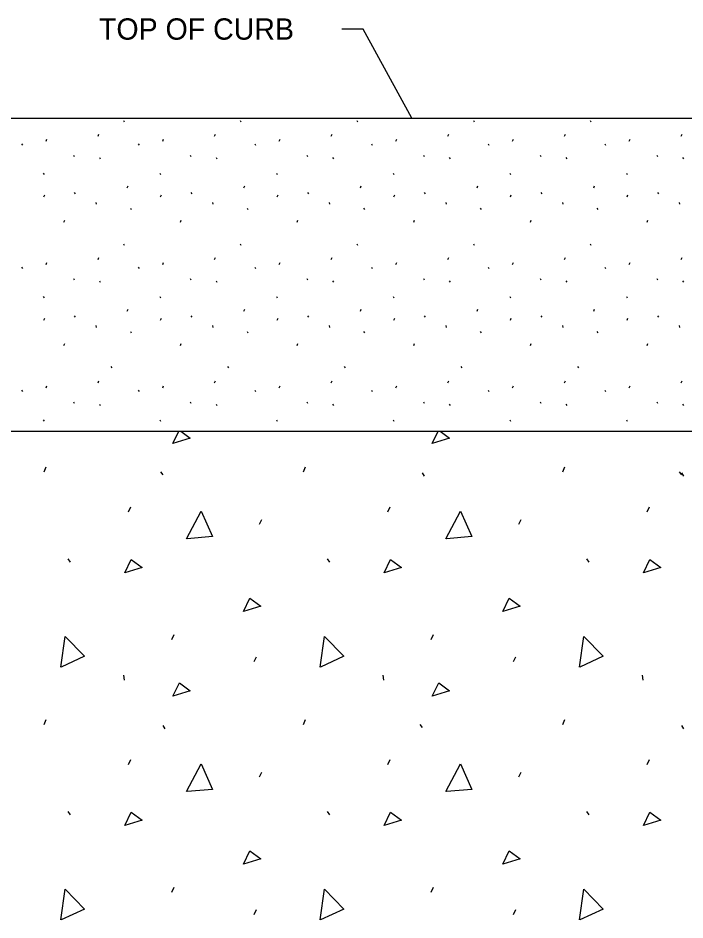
# Model space of a CAD drawing. Extents: x 99988 to 100172, y 99995 to 100047.
# Drawn here: x 100004.171 to 100006.359, y 100005.482 to 100008.443 of the extents above; entities that cross this region are included whole.
import ezdxf

# ---------------------------------------------------------------- set-up
doc = ezdxf.new("R2010")
doc.units = 0
for name, color, linetype in [('Level 1', 7, 'Continuous'), ('Level 15', 7, 'Continuous'), ('Level 2', 7, 'Continuous'), ('Level 20', 7, 'Continuous'), ('Level 3', 7, 'Continuous')]:
    doc.layers.add(name, color=color, linetype=linetype)

msp = doc.modelspace()

# ---------------------------------------------------------------- linework, layer by layer
at = {"layer": 'Level 1'}
msp.add_line((100000.585, 100008.1139), (100009.7707, 100008.1139), dxfattribs=at)
at = {"layer": 'Level 15'}
msp.add_lwpolyline([(100005.4633, 100008.1139), (100005.3031, 100008.407), (100005.2331, 100008.407)], dxfattribs=at)
at = {"layer": 'Level 2'}
msp.add_line((100000.585, 100007.0869), (100009.7707, 100007.0869), dxfattribs=at)
at = {"layer": 'Level 3'}
for p, q in [((100004.5171, 100008.1069), (100004.52, 100008.1026)), ((100004.8998, 100008.1069), (100004.9026, 100008.1026)), ((100005.2824, 100008.1069), (100005.2853, 100008.1026)), ((100005.665, 100008.1069), (100005.6679, 100008.1026)), ((100006.0477, 100008.1069), (100006.0506, 100008.1026)), ((100004.4337, 100008.0553), (100004.4366, 100008.0617)), ((100004.8164, 100008.0553), (100004.8192, 100008.0617)), ((100005.199, 100008.0553), (100005.2019, 100008.0617)), ((100005.5816, 100008.0553), (100005.5845, 100008.0617)), ((100005.9643, 100008.0553), (100005.9672, 100008.0617)), ((100006.3469, 100008.0553), (100006.3498, 100008.0617)), ((100004.1827, 100008.0303), (100004.1856, 100008.026)), ((100004.2632, 100008.0387), (100004.2661, 100008.0452)), ((100004.5654, 100008.0303), (100004.5683, 100008.026)), ((100004.6459, 100008.0387), (100004.6488, 100008.0452)), ((100004.948, 100008.0303), (100004.9509, 100008.026)), ((100005.0285, 100008.0387), (100005.0314, 100008.0452)), ((100005.3307, 100008.0303), (100005.3335, 100008.026)), ((100005.4112, 100008.0387), (100005.414, 100008.0452)), ((100005.7133, 100008.0303), (100005.7162, 100008.026)), ((100005.7938, 100008.0387), (100005.7967, 100008.0452)), ((100006.0959, 100008.0303), (100006.0988, 100008.026)), ((100006.1764, 100008.0387), (100006.1793, 100008.0452)), ((100004.3532, 100007.9927), (100004.356, 100007.9884)), ((100004.4382, 100007.9849), (100004.441, 100007.9806)), ((100004.7358, 100007.9927), (100004.7387, 100007.9884)), ((100004.8208, 100007.9849), (100004.8237, 100007.9806)), ((100005.1184, 100007.9927), (100005.1213, 100007.9884)), ((100005.2034, 100007.9849), (100005.2063, 100007.9806)), ((100005.5011, 100007.9927), (100005.504, 100007.9884)), ((100005.5861, 100007.9849), (100005.589, 100007.9806)), ((100005.8837, 100007.9927), (100005.8866, 100007.9884)), ((100005.9687, 100007.9849), (100005.9716, 100007.9806)), ((100006.2664, 100007.9927), (100006.2692, 100007.9884)), ((100006.3514, 100007.9849), (100006.3542, 100007.9806)), ((100004.2537, 100007.9338), (100004.2566, 100007.9295)), ((100004.6363, 100007.9338), (100004.6392, 100007.9295)), ((100005.019, 100007.9338), (100005.0218, 100007.9295)), ((100005.4016, 100007.9338), (100005.4045, 100007.9295)), ((100005.7842, 100007.9338), (100005.7871, 100007.9295)), ((100006.1669, 100007.9338), (100006.1698, 100007.9295)), ((100004.5294, 100007.8855), (100004.5322, 100007.892)), ((100004.912, 100007.8855), (100004.9149, 100007.892)), ((100005.2946, 100007.8855), (100005.2975, 100007.892)), ((100005.6773, 100007.8855), (100005.6802, 100007.892)), ((100006.0599, 100007.8855), (100006.0628, 100007.892)), ((100004.2561, 100007.856), (100004.2589, 100007.8625)), ((100004.3559, 100007.87), (100004.3587, 100007.8656)), ((100004.6387, 100007.856), (100004.6416, 100007.8625)), ((100004.7385, 100007.87), (100004.7414, 100007.8656)), ((100005.0213, 100007.856), (100005.0242, 100007.8625)), ((100005.1211, 100007.87), (100005.124, 100007.8656)), ((100005.404, 100007.856), (100005.4069, 100007.8625)), ((100005.5038, 100007.87), (100005.5067, 100007.8656)), ((100005.7866, 100007.856), (100005.7895, 100007.8625)), ((100005.8864, 100007.87), (100005.8893, 100007.8656)), ((100006.1693, 100007.856), (100006.1721, 100007.8625)), ((100006.2691, 100007.87), (100006.2719, 100007.8656)), ((100004.4271, 100007.8379), (100004.4278, 100007.8315)), ((100004.5398, 100007.8189), (100004.5427, 100007.8146)), ((100004.8097, 100007.8379), (100004.8104, 100007.8315)), ((100004.9225, 100007.8189), (100004.9253, 100007.8146)), ((100005.1923, 100007.8379), (100005.1931, 100007.8315)), ((100005.3051, 100007.8189), (100005.308, 100007.8146)), ((100005.575, 100007.8379), (100005.5757, 100007.8315)), ((100005.6878, 100007.8189), (100005.6906, 100007.8146)), ((100005.9576, 100007.8379), (100005.9583, 100007.8315)), ((100006.0704, 100007.8189), (100006.0733, 100007.8146)), ((100006.3403, 100007.8379), (100006.341, 100007.8315)), ((100004.3215, 100007.7726), (100004.3244, 100007.779)), ((100004.7042, 100007.7726), (100004.707, 100007.779)), ((100005.0868, 100007.7726), (100005.0897, 100007.779)), ((100005.4694, 100007.7726), (100005.4723, 100007.779)), ((100005.8521, 100007.7726), (100005.855, 100007.779)), ((100006.2347, 100007.7726), (100006.2376, 100007.779)), ((100004.5171, 100007.7022), (100004.52, 100007.6979)), ((100004.8998, 100007.7022), (100004.9026, 100007.6979)), ((100005.2824, 100007.7022), (100005.2853, 100007.6979)), ((100005.665, 100007.7022), (100005.6679, 100007.6979)), ((100006.0477, 100007.7022), (100006.0506, 100007.6979)), ((100004.2632, 100007.634), (100004.2661, 100007.6405)), ((100004.4337, 100007.6505), (100004.4366, 100007.657)), ((100004.6459, 100007.634), (100004.6488, 100007.6405)), ((100004.8164, 100007.6505), (100004.8192, 100007.657)), ((100005.0285, 100007.634), (100005.0314, 100007.6405)), ((100005.199, 100007.6505), (100005.2019, 100007.657)), ((100005.4112, 100007.634), (100005.414, 100007.6405)), ((100005.5816, 100007.6505), (100005.5845, 100007.657)), ((100005.7938, 100007.634), (100005.7967, 100007.6405)), ((100005.9643, 100007.6505), (100005.9672, 100007.657)), ((100006.1764, 100007.634), (100006.1793, 100007.6405)), ((100006.3469, 100007.6505), (100006.3498, 100007.657)), ((100004.1827, 100007.6256), (100004.1856, 100007.6213)), ((100004.5654, 100007.6256), (100004.5683, 100007.6213)), ((100004.948, 100007.6256), (100004.9509, 100007.6213)), ((100005.3307, 100007.6256), (100005.3335, 100007.6213)), ((100005.7133, 100007.6256), (100005.7162, 100007.6213)), ((100006.0959, 100007.6256), (100006.0988, 100007.6213)), ((100004.3532, 100007.588), (100004.356, 100007.5836)), ((100004.7358, 100007.588), (100004.7387, 100007.5836)), ((100005.1184, 100007.588), (100005.1213, 100007.5836)), ((100005.5011, 100007.588), (100005.504, 100007.5836)), ((100005.8837, 100007.588), (100005.8866, 100007.5836)), ((100006.2664, 100007.588), (100006.2692, 100007.5836)), ((100004.4382, 100007.5802), (100004.441, 100007.5759)), ((100004.8208, 100007.5802), (100004.8237, 100007.5759)), ((100005.2034, 100007.5802), (100005.2063, 100007.5759)), ((100005.5861, 100007.5802), (100005.589, 100007.5759)), ((100005.9687, 100007.5802), (100005.9716, 100007.5759)), ((100006.3514, 100007.5802), (100006.3542, 100007.5759)), ((100004.2537, 100007.5291), (100004.2566, 100007.5248)), ((100004.6363, 100007.5291), (100004.6392, 100007.5248)), ((100005.019, 100007.5291), (100005.0218, 100007.5248)), ((100005.4016, 100007.5291), (100005.4045, 100007.5248)), ((100005.7842, 100007.5291), (100005.7871, 100007.5248)), ((100006.1669, 100007.5291), (100006.1698, 100007.5248)), ((100004.3559, 100007.4652), (100004.3587, 100007.4609)), ((100004.5294, 100007.4808), (100004.5322, 100007.4873)), ((100004.7385, 100007.4652), (100004.7414, 100007.4609)), ((100004.912, 100007.4808), (100004.9149, 100007.4873)), ((100005.1211, 100007.4652), (100005.124, 100007.4609)), ((100005.2946, 100007.4808), (100005.2975, 100007.4873)), ((100005.5038, 100007.4652), (100005.5067, 100007.4609)), ((100005.6773, 100007.4808), (100005.6802, 100007.4873)), ((100005.8864, 100007.4652), (100005.8893, 100007.4609)), ((100006.0599, 100007.4808), (100006.0628, 100007.4873)), ((100006.2691, 100007.4652), (100006.2719, 100007.4609)), ((100004.2561, 100007.4513), (100004.2589, 100007.4578)), ((100004.4271, 100007.4332), (100004.4278, 100007.4268)), ((100004.6387, 100007.4513), (100004.6416, 100007.4578)), ((100004.8097, 100007.4332), (100004.8104, 100007.4268)), ((100005.0213, 100007.4513), (100005.0242, 100007.4578)), ((100005.1923, 100007.4332), (100005.1931, 100007.4268)), ((100005.404, 100007.4513), (100005.4069, 100007.4578)), ((100005.575, 100007.4332), (100005.5757, 100007.4268)), ((100005.7866, 100007.4513), (100005.7895, 100007.4578)), ((100005.9576, 100007.4332), (100005.9583, 100007.4268)), ((100006.1693, 100007.4513), (100006.1721, 100007.4578)), ((100006.3403, 100007.4332), (100006.341, 100007.4268)), ((100004.5398, 100007.4142), (100004.5427, 100007.4098)), ((100004.9225, 100007.4142), (100004.9253, 100007.4098)), ((100005.3051, 100007.4142), (100005.308, 100007.4098)), ((100005.6878, 100007.4142), (100005.6906, 100007.4098)), ((100006.0704, 100007.4142), (100006.0733, 100007.4098)), ((100004.3215, 100007.3679), (100004.3244, 100007.3743)), ((100004.7042, 100007.3679), (100004.707, 100007.3743)), ((100005.0868, 100007.3679), (100005.0897, 100007.3743)), ((100005.4694, 100007.3679), (100005.4723, 100007.3743)), ((100005.8521, 100007.3679), (100005.855, 100007.3743)), ((100006.2347, 100007.3679), (100006.2376, 100007.3743)), ((100004.4762, 100007.2991), (100004.479, 100007.2948)), ((100004.8588, 100007.2991), (100004.8617, 100007.2948)), ((100005.2414, 100007.2991), (100005.2443, 100007.2948)), ((100005.6241, 100007.2991), (100005.627, 100007.2948)), ((100006.0067, 100007.2991), (100006.0096, 100007.2948)), ((100004.2632, 100007.2293), (100004.2661, 100007.2358)), ((100004.4337, 100007.2458), (100004.4366, 100007.2523)), ((100004.6459, 100007.2293), (100004.6488, 100007.2358)), ((100004.8164, 100007.2458), (100004.8192, 100007.2523)), ((100005.0285, 100007.2293), (100005.0314, 100007.2358)), ((100005.199, 100007.2458), (100005.2019, 100007.2523)), ((100005.4112, 100007.2293), (100005.414, 100007.2358)), ((100005.5816, 100007.2458), (100005.5845, 100007.2523)), ((100005.7938, 100007.2293), (100005.7967, 100007.2358)), ((100005.9643, 100007.2458), (100005.9672, 100007.2523)), ((100006.1764, 100007.2293), (100006.1793, 100007.2358)), ((100006.3469, 100007.2458), (100006.3498, 100007.2523)), ((100004.1827, 100007.2209), (100004.1856, 100007.2166)), ((100004.5654, 100007.2209), (100004.5683, 100007.2166)), ((100004.948, 100007.2209), (100004.9509, 100007.2166)), ((100005.3307, 100007.2209), (100005.3335, 100007.2166)), ((100005.7133, 100007.2209), (100005.7162, 100007.2166)), ((100006.0959, 100007.2209), (100006.0988, 100007.2166)), ((100004.3532, 100007.1833), (100004.356, 100007.1789)), ((100004.4382, 100007.1755), (100004.441, 100007.1711)), ((100004.7358, 100007.1833), (100004.7387, 100007.1789)), ((100004.8208, 100007.1755), (100004.8237, 100007.1711)), ((100005.1184, 100007.1833), (100005.1213, 100007.1789)), ((100005.2034, 100007.1755), (100005.2063, 100007.1711)), ((100005.5011, 100007.1833), (100005.504, 100007.1789)), ((100005.5861, 100007.1755), (100005.589, 100007.1711)), ((100005.8837, 100007.1833), (100005.8866, 100007.1789)), ((100005.9687, 100007.1755), (100005.9716, 100007.1711)), ((100006.2664, 100007.1833), (100006.2692, 100007.1789)), ((100006.3514, 100007.1755), (100006.3542, 100007.1711)), ((100004.2537, 100007.1244), (100004.2566, 100007.1201)), ((100004.6363, 100007.1244), (100004.6392, 100007.1201)), ((100005.019, 100007.1244), (100005.0218, 100007.1201)), ((100005.4016, 100007.1244), (100005.4045, 100007.1201)), ((100005.7842, 100007.1244), (100005.7871, 100007.1201)), ((100006.1669, 100007.1244), (100006.1698, 100007.1201)), ((100004.2569, 100006.9538), (100004.264, 100006.9698)), ((100005.1077, 100006.9538), (100005.1148, 100006.9698)), ((100005.9584, 100006.9538), (100005.9655, 100006.9698)), ((100004.6388, 100006.9538), (100004.6459, 100006.9432)), ((100005.4966, 100006.9498), (100005.5037, 100006.9391)), ((100006.3403, 100006.9538), (100006.3474, 100006.9432)), ((100006.3474, 100006.9498), (100006.3545, 100006.9391)), ((100004.534, 100006.8222), (100004.5411, 100006.8382)), ((100005.3847, 100006.8222), (100005.3918, 100006.8382)), ((100006.2355, 100006.8222), (100006.2426, 100006.8382)), ((100004.9638, 100006.7813), (100004.9709, 100006.7973)), ((100005.8146, 100006.7813), (100005.8217, 100006.7973)), ((100004.3351, 100006.6677), (100004.3422, 100006.657)), ((100005.1858, 100006.6677), (100005.1929, 100006.657)), ((100006.0366, 100006.6677), (100006.0437, 100006.657)), ((100004.6761, 100006.403), (100004.6832, 100006.419)), ((100005.5269, 100006.403), (100005.534, 100006.419)), ((100004.9461, 100006.3302), (100004.9532, 100006.3462)), ((100005.7968, 100006.3302), (100005.8039, 100006.3462)), ((100004.5176, 100006.2856), (100004.5193, 100006.2696)), ((100005.3683, 100006.2856), (100005.3701, 100006.2696)), ((100006.2191, 100006.2856), (100006.2208, 100006.2696)), ((100004.2569, 100006.1242), (100004.264, 100006.1402)), ((100005.1077, 100006.1242), (100005.1148, 100006.1402)), ((100005.9584, 100006.1242), (100005.9655, 100006.1402)), ((100004.6459, 100006.1201), (100004.653, 100006.1095)), ((100005.4895, 100006.1242), (100005.4966, 100006.1135)), ((100006.3474, 100006.1201), (100006.3545, 100006.1095)), ((100004.534, 100005.9925), (100004.5411, 100006.0085)), ((100005.3847, 100005.9925), (100005.3918, 100006.0085)), ((100006.2355, 100005.9925), (100006.2426, 100006.0085)), ((100004.9638, 100005.9517), (100004.9709, 100005.9677)), ((100005.8146, 100005.9517), (100005.8217, 100005.9677)), ((100004.3351, 100005.838), (100004.3422, 100005.8274)), ((100005.1858, 100005.838), (100005.1929, 100005.8274)), ((100006.0366, 100005.838), (100006.0437, 100005.8274)), ((100004.6761, 100005.5734), (100004.6832, 100005.5894)), ((100005.5269, 100005.5734), (100005.534, 100005.5894)), ((100004.9461, 100005.5006), (100004.9532, 100005.5166)), ((100005.7968, 100005.5006), (100005.8039, 100005.5166))]:
    msp.add_line(p, q, dxfattribs=at)
for points in [[(100004.7058, 100007.0869), (100004.7365, 100007.0639), (100004.6797, 100007.0462)], [(100004.6797, 100007.0462), (100004.6992, 100007.0869)], [(100005.5566, 100007.0869), (100005.5872, 100007.0639), (100005.5304, 100007.0462)], [(100005.5304, 100007.0462), (100005.55, 100007.0869)], [(100004.7241, 100006.7334), (100004.772, 100006.824), (100004.8093, 100006.7405), (100004.7258, 100006.7334)], [(100005.5748, 100006.7334), (100005.6228, 100006.824), (100005.6601, 100006.7405), (100005.5766, 100006.7334)], [(100004.5216, 100006.6215), (100004.5429, 100006.6659), (100004.5784, 100006.6392), (100004.5216, 100006.6215)], [(100005.3723, 100006.6215), (100005.3936, 100006.6659), (100005.4291, 100006.6392), (100005.3723, 100006.6215)], [(100006.2231, 100006.6215), (100006.2444, 100006.6659), (100006.2799, 100006.6392), (100006.2231, 100006.6215)], [(100004.9109, 100006.4945), (100004.9322, 100006.5389), (100004.9677, 100006.5123), (100004.9109, 100006.4945)], [(100005.7616, 100006.4945), (100005.7829, 100006.5389), (100005.8185, 100006.5123), (100005.7616, 100006.4945)], [(100004.3114, 100006.3118), (100004.3255, 100006.4133), (100004.3891, 100006.3477), (100004.313, 100006.3124)], [(100005.1621, 100006.3118), (100005.1762, 100006.4133), (100005.2398, 100006.3477), (100005.1638, 100006.3124)], [(100006.0129, 100006.3118), (100006.027, 100006.4133), (100006.0906, 100006.3477), (100006.0145, 100006.3124)], [(100004.6797, 100006.2165), (100004.701, 100006.261), (100004.7365, 100006.2343), (100004.6797, 100006.2165)], [(100005.5304, 100006.2165), (100005.5517, 100006.261), (100005.5872, 100006.2343), (100005.5304, 100006.2165)], [(100004.7241, 100005.9037), (100004.772, 100005.9943), (100004.8093, 100005.9109), (100004.7258, 100005.9037)], [(100005.5748, 100005.9037), (100005.6228, 100005.9943), (100005.6601, 100005.9109), (100005.5766, 100005.9037)], [(100004.5216, 100005.7919), (100004.5429, 100005.8363), (100004.5784, 100005.8096), (100004.5216, 100005.7919)], [(100005.3723, 100005.7919), (100005.3936, 100005.8363), (100005.4291, 100005.8096), (100005.3723, 100005.7919)], [(100006.2231, 100005.7919), (100006.2444, 100005.8363), (100006.2799, 100005.8096), (100006.2231, 100005.7919)], [(100004.9109, 100005.6649), (100004.9322, 100005.7093), (100004.9677, 100005.6827), (100004.9109, 100005.6649)], [(100005.7616, 100005.6649), (100005.7829, 100005.7093), (100005.8185, 100005.6827), (100005.7616, 100005.6649)], [(100004.3114, 100005.4822), (100004.3255, 100005.5837), (100004.3891, 100005.518), (100004.313, 100005.4828)], [(100005.1621, 100005.4822), (100005.1762, 100005.5837), (100005.2398, 100005.518), (100005.1638, 100005.4828)], [(100006.0129, 100005.4822), (100006.027, 100005.5837), (100006.0906, 100005.518), (100006.0145, 100005.4828)]]:
    msp.add_lwpolyline(points, dxfattribs=at)

# ---------------------------------------------------------------- texts
at = {"layer": 'Level 20'}
msp.add_text('TOP OF CURB', height=0.07, dxfattribs=at).set_placement((100004.4369, 100008.372))

doc.saveas('drawing.dxf')
